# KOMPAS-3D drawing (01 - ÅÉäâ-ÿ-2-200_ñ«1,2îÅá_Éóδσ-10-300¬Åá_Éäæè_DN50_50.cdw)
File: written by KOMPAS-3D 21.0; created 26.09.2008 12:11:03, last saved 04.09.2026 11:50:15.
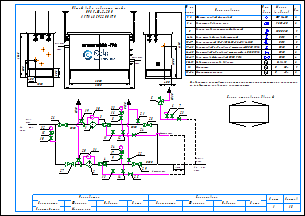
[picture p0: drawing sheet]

Sheets 1-2: A3, landscape

Document properties: Наименование: Макро:21; Автор: RaskoAdmin; Форматы листов документа: 2xA3; Полное имя файла: \\UR38nt01\Departments\КТО\КБ ПУРДГ\Заявки\Прайс-лист на типовые шкафы ГРПШ\ПРДГ_стандарт_20_03_2026\ПРДГ с РДСК\ПРДГ-Ш-2-200_до1,2МПа_Рвых-10-300кПа_РДСК_DN50_50.cdw

Title block, sheet 1: Наименование: Пункт учета газа / ПУГ-Ш-400-Р / ЛГТИ.485922.001ТУ; designation: ЛГТИ.03.4411141; sheet number: 1; Количество листов документа: 2; organisation: ООО "ЭЛЬСТЕР Газэлектроника"; Форматы листов документа: A3; stored path: C:\Рабочие документы\Компас\ПУГ\Схема.cdw; Разработал: Устинов; Проверил: Кошкин; Утвердил: Кошкин
Title block, sheet 2: sheet number: 2; stored path: D:\Рабочие документы\Заявки\ПУРДГ\ПУРДГ-ШУЭО-2-100-Р 4411220.cdw; designation, second copy: ЛГТИ.03.4411141-

Views: Вид 1, Вид 2
Referenced files: wcvoit.frw
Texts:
  Normal
  Вход
  газа
  PDI
  Выход
  Р=     кПа
  DN50
  DN20
  Импульс DN20
  ≥5DN
  HYSWLongFangSong
  № на
  схеме
  Усл.
  обозн.
  Марка
  (модель)
  Кол.
  Фильтр газовый фланцевый
  ФГ 16-50
  Регулятор давления газа
  РДCК-50
  Клапан предохранительный сбросной
  КПС DN20
  Кран шаровой газовый латунный
  DN15
  Кран кнопочный VE-РАСКО-НЗ-1,6-G1/2-М20
  Кран шаровой "под приварку" штуцерный DN20 PN16
  Кран шаровой "под приварку" штуцерный п/п DN20 PN16
  Кран шаровой фланцевый DN50 PN16
  Индикатор перепада давления
  Delta 15
  Манометр
  Манометр-напоромер
  0...     МПа
  0...     кПа
  Общий вид и габариты шкафа
  ПРДГ-Ш-2-200
  Выход газа
  Вход газа
  Схема открывания дверей
  Р=       МПа
  logo-rasko-ge.png
  Предприятие изготовитель может заменять комплектующие на аналогичные,
  не ухудшающие заявленных характеристик.
  Должность
  Конструктор
  Фамилия
  Подпись
  Дата
  Согласовано
  Максимкин
  Лист
  Листов
  POLYLINE_STYLE_0.18_RGB_0_0_0
  POLYLINE_STYLE_0.50_RGB_0_0_0
  POLYLINE_STYLE_0.34_RGB_0_0_0
  PHANTOM_RGB_0_0_0_SC_1_THICK_0.18
  K5LT_THIN_RGB_0_0_0_THICK_0.18
  K5LT32769_RGB_0_0_0_THICK_0.18
  K5LT12_RGB_0_0_0_SC_1_THICK_0.18
  K5LT_DASHED_RGB_0_0_0_SC_1_THICK_0.18
  ACISOTGL_RGB_0_0_0_SC_0.8_THICK_0.25
  CONTINUOUS_RGB_0_127_31_THICK_0.3
  CONTINUOUS_RGB_0_0_255_THICK_0.35
  CONTINUOUS_RGB_255_0_0_THICK_0.35
  POLYLINE_STYLE_0.25_RGB_0_0_0
  CONTINUOUS_RGB_0_0_0_THICK_0.5
  POLYLINE_STYLE_0.35_RGB_0_0_255
  CONTINUOUS_RGB_0_0_0_THICK_0.4
  CONTINUOUS_RGB_0_0_0_THICK_0.35
  Без оформления
Dimensions and other numbers on the sheet: 1; 2; 3; 4; 5; 10; 27; 28; 29; 23; 8; 12; 19; 20; 21; 22; 25; 24; 30; 31; 15; 16; 26; 6; 7; 11; 14; 13; 33; 1, 2; 3, 4; 6-14; 9; 15-17; 19-23; 24-25; 26-29; 30-31; 32; 33-34; 1000; 400; 1050; 500; 305; 2000; 4130; 1565; 2300; 17; 34; 18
